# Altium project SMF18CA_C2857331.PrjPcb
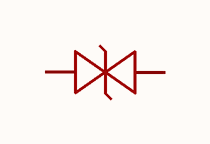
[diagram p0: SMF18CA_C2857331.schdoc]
1 sheet, 1 parts. Net scope: global (net labels, ports and power ports of the same name join across sheets).

## Sheet SMF18CA_C2857331.schdoc
size 127 x 101 mm

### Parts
D?  smf18ca_c2857331  [SMF_L2.8-W1.8-LS3.7-BI]  (value not drawn)

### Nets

Not connected (* = marked no-connect by the designer): D? 1(C) 2(A)

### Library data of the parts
D? = smf18ca_c2857331: 极性:双向;反向截止电压(Vrwm):18V;钳位电压:29.2V;峰值脉冲电流(Ipp):6.8A;峰值脉冲功率(Ppp):200W@10/1000us;击穿电压(VBR):20V;; Manufacturer: JSMSEMI(杰盛微); AddInBom: yes; ModelId: 4c5053f487124fd992cc1df21c047b05; ModelTransform: 145.669,70.866,0,0,0,0,0,0,0; Polarity: 双向; Reverse Stand-Off Voltage (Vrwm): 18V; Clamping Voltage: 29.2V; Peak Pulse Current (Ipp): 6.8A; Voltage - Breakdown: 20V; Reverse Leakage Current (Ir): 1uA; Number of Channels: 单路; Type: TVS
